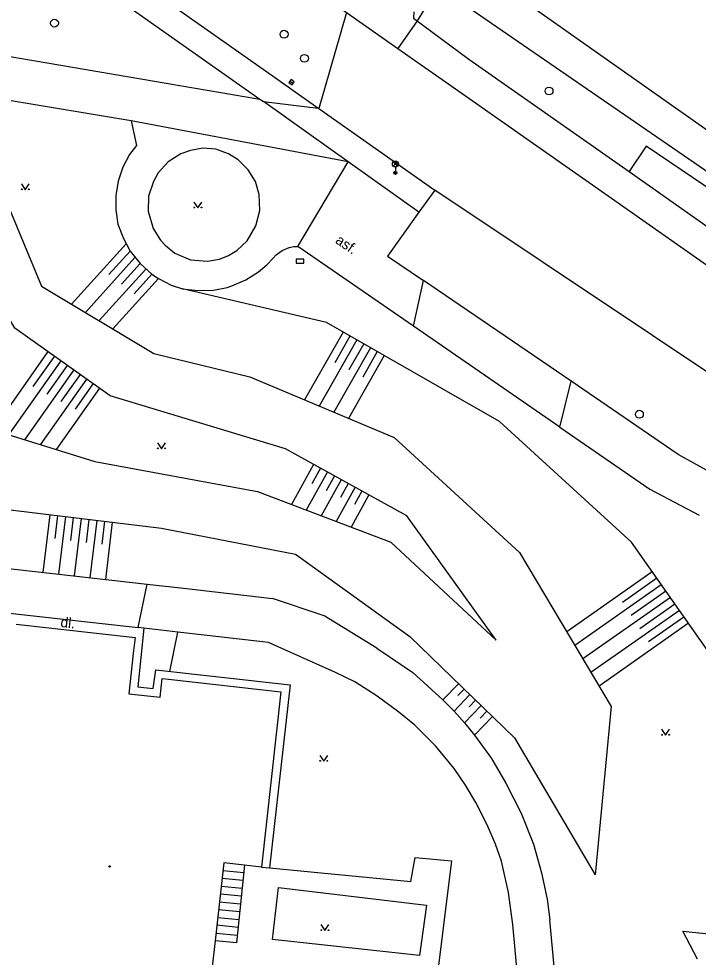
# Model space of a CAD drawing. Extents: x -602419 to -601554, y -1162937 to -1162362.
# Drawn here: x -602003.4 to -601960.3, y -1162582 to -1162522.5 of the extents above; entities that cross this region are included whole.
import ezdxf

# ---------------------------------------------------------------- set-up
doc = ezdxf.new("R2010")
doc.units = 0
doc.layers.add('Podklad', color=7, linetype='Continuous')

msp = doc.modelspace()

# ---------------------------------------------------------------- linework, layer by layer
at = {"layer": 'Podklad'}
for p, q in [((-602001.1665, -1162516.3917), (-601988.13, -1162525.56)), ((-601998.3077, -1162520.4323), (-601988.11, -1162527.62)), ((-601986.2125, -1162526.4685), (-601986.0075, -1162526.6115)), ((-601979.6525, -1162531.86), (-601979.3875, -1162531.595)), ((-601979.6525, -1162531.595), (-601979.3875, -1162531.86)), ((-601979.52, -1162531.915), (-601979.52, -1162532.29))]:
    msp.add_line(p, q, dxfattribs=at)
for points in [[(-601977.7199, -1162516.9), (-601956.9099, -1162531.58), (-601954.44, -1162533.26), (-601952.87, -1162534.1599)], [(-601984.54, -1162520.75), (-601979.57, -1162524.25), (-601975.29, -1162527.25)], [(-601934.5953, -1162546.3375), (-601934.4053, -1162544.2963), (-601934.395, -1162544.1839), (-601934.035, -1162541.6329), (-601941.491, -1162540.521), (-601946.887, -1162539.0499), (-601952.218, -1162537.284), (-601953.5449, -1162536.4029), (-601953.8289, -1162536.2141), (-601956.502, -1162534.4389), (-601976.81, -1162520.475), (-601978.14, -1162522.6591), (-601979.356, -1162524.4)], [(-601987.89, -1162527.76), (-601984.4098, -1162528.1838), (-601984.36, -1162528.1899), (-601982.6096, -1162522.1094)], [(-601978.35, -1162522.08), (-601978.37, -1162522.49), (-601974.85, -1162525.08)], [(-602011.79, -1162523.58), (-601988.11, -1162527.62)], [(-601974.85, -1162525.08), (-601964.68, -1162532.21)], [(-601988.13, -1162525.56), (-601986.98, -1162526.37)], [(-601986.98, -1162526.37), (-601985.88, -1162527.15)], [(-601996.29, -1162529), (-602007.08, -1162527.2)], [(-602007.08, -1162527.2), (-602001.98, -1162539.48), (-601994.84, -1162543.74), (-601988.75, -1162545.23), (-601979.6, -1162549.08), (-601971.65, -1162556.37), (-601965.83, -1162566.14), (-601966.84, -1162576.81)], [(-601985.88, -1162527.15), (-601977.02, -1162533.38), (-601978.04, -1162534.79)], [(-601975.29, -1162527.25), (-601965.81, -1162533.9)], [(-601988.11, -1162527.62), (-601987.89, -1162527.76)], [(-601985.71, -1162536.9699), (-601982.51, -1162531.59), (-601986.26, -1162528.9299), (-601986.49, -1162528.7699), (-601987.89, -1162527.76)], [(-601996.29, -1162529), (-601995.95, -1162530.55)], [(-601978.04, -1162534.79), (-601982.51, -1162531.59), (-601996.29, -1162529)], [(-601995.95, -1162530.55), (-601996.38, -1162531.13), (-601996.82, -1162531.94), (-601997.11, -1162532.81), (-601997.25, -1162533.7199), (-601997.26, -1162534.64), (-601997.13, -1162535.55), (-601996.78, -1162536.46), (-601996.35, -1162537.26), (-601995.7199, -1162538.05), (-601994.9699, -1162538.7199), (-601994.55, -1162539), (-601993.75, -1162539.4099), (-601993.03, -1162539.64)], [(-601992.51, -1162530.87), (-601993.13, -1162531.09)], [(-601991.73, -1162530.7199), (-601992.51, -1162530.87)], [(-601990.9099, -1162530.8), (-601991.73, -1162530.7199)], [(-601990.1, -1162531.08), (-601990.9099, -1162530.8)], [(-601963.6, -1162530.6), (-601964.68, -1162532.21)], [(-601963.6, -1162530.6), (-601964.68, -1162532.21)], [(-601957.74, -1162534.57), (-601963.6, -1162530.6)], [(-601993.13, -1162531.09), (-601993.93, -1162531.6)], [(-601989.5, -1162531.4699), (-601990.1, -1162531.08)], [(-601988.87, -1162532.1), (-601989.5, -1162531.4699)], [(-601993.93, -1162531.6), (-601994.58, -1162532.3)], [(-601994.58, -1162532.3), (-601994.86, -1162532.85)], [(-601988.4, -1162532.83), (-601988.87, -1162532.1)], [(-601964.68, -1162532.21), (-601958.95, -1162536.24)], [(-602003.25, -1162532.985), (-602003, -1162533.36), (-602002.75, -1162532.985)], [(-601994.86, -1162532.85), (-601995.18, -1162533.76)], [(-601988.1599, -1162533.6599), (-601988.4, -1162532.83)], [(-601995.18, -1162533.76), (-601995.2, -1162534.7199)], [(-601988.13, -1162534.67), (-601988.1599, -1162533.6599)], [(-601956.34, -1162547.2), (-601977.02, -1162533.38)], [(-601992.3, -1162534.145), (-601992.05, -1162534.52), (-601991.8, -1162534.145)], [(-601965.81, -1162533.9), (-601958, -1162539.37), (-601957.2, -1162539.88)], [(-601973.12, -1162561.93), (-601978.8, -1162554.04), (-601986.49, -1162549.8), (-601997.61, -1162546.43), (-602003.6599, -1162542.15), (-602007.98, -1162534.7199)], [(-601995.2, -1162534.7199), (-601994.89, -1162535.83)], [(-601988.37, -1162535.65), (-601988.13, -1162534.67)], [(-601978.04, -1162534.79), (-601980.03, -1162537.57), (-601977.73, -1162539.11)], [(-601988.92, -1162536.61), (-601988.37, -1162535.65)], [(-601994.89, -1162535.83), (-601994.42, -1162536.55)], [(-601996.61, -1162536.8), (-602000.07, -1162540.62)], [(-601994.42, -1162536.55), (-601994.13, -1162536.87)], [(-601989.57, -1162537.21), (-601988.92, -1162536.61)], [(-601996.35, -1162537.26), (-601997.69, -1162538.73)], [(-601994.13, -1162536.87), (-601993.52, -1162537.39)], [(-601993.52, -1162537.39), (-601992.52, -1162537.81)], [(-601993.03, -1162539.64), (-601992.05, -1162539.75), (-601991.05, -1162539.73), (-601990.19, -1162539.56), (-601989.89, -1162539.45), (-601989.01, -1162539.07), (-601988.2, -1162538.56), (-601987.68, -1162538.13), (-601987.27, -1162537.7), (-601987.09, -1162537.49), (-601986.7, -1162537.21), (-601986.26, -1162537.02), (-601985.9699, -1162536.96), (-601985.71, -1162536.9699)], [(-601990.1, -1162537.53), (-601989.57, -1162537.21)], [(-601978.38, -1162542.02), (-601985.71, -1162536.9699)], [(-601996.05, -1162537.67), (-601999.19, -1162541.14)], [(-601992.52, -1162537.81), (-601991.45, -1162537.9)], [(-601991.45, -1162537.9), (-601990.68, -1162537.76)], [(-601990.68, -1162537.76), (-601990.1, -1162537.53)], [(-601995.36, -1162538.4), (-601998.32, -1162541.6599)], [(-601995.7199, -1162538.05), (-601996.89, -1162539.35)], [(-601994.55, -1162539), (-601997.44, -1162542.19)], [(-601994.9699, -1162538.7199), (-601996.1, -1162539.96)], [(-601978.38, -1162542.02), (-601977.73, -1162539.11)], [(-601968.36, -1162545.51), (-601977.73, -1162539.11)], [(-601959.05, -1162563.54), (-601964.54, -1162555.71), (-601972.92, -1162548.05), (-601983.89, -1162541.79), (-601993.03, -1162539.64)], [(-601969.08, -1162548.43), (-601978.38, -1162542.02)], [(-601982.84, -1162542.39), (-601985.29, -1162546.69)], [(-601982.4, -1162542.64), (-601983.37, -1162544.34)], [(-601981.9699, -1162542.89), (-601984.36, -1162547.08)], [(-601981.1, -1162543.38), (-601983.43, -1162547.4699)], [(-601981.53, -1162543.13), (-601982.48, -1162544.79)], [(-602008.99, -1162543.69), (-602004.8, -1162548.68), (-601998.59, -1162550.6), (-601988.27, -1162552.51), (-601979.81, -1162555.7199), (-601973.12, -1162561.93)], [(-602001.56, -1162543.63), (-602004.98, -1162548.4699)], [(-602001.15, -1162543.92), (-602002.52, -1162545.85)], [(-601980.23, -1162543.88), (-601982.5, -1162547.86)], [(-601980.67, -1162543.63), (-601981.59, -1162545.24)], [(-602000.74, -1162544.21), (-602004.07, -1162548.9099)], [(-602000.34, -1162544.5), (-602001.63, -1162546.33)], [(-601999.93, -1162544.79), (-602003.06, -1162549.2199)], [(-601999.52, -1162545.08), (-602000.74, -1162546.8)], [(-601999.11, -1162545.37), (-602002.06, -1162549.53)], [(-601998.7, -1162545.6599), (-601999.84, -1162547.27)], [(-601969.08, -1162548.43), (-601968.36, -1162545.51)], [(-601959.59, -1162551.26), (-601961.57, -1162550.15), (-601968.36, -1162545.51)], [(-601998.3, -1162545.94), (-602001.05, -1162549.84)], [(-601969.08, -1162548.43), (-601963.38, -1162552.36), (-601960.25, -1162553.99)], [(-601994.61, -1162549.415), (-601994.36, -1162549.79), (-601994.11, -1162549.415)], [(-601984.71, -1162550.78), (-601986.11, -1162553.33)], [(-601984.27, -1162551.02), (-601984.82, -1162552.02)], [(-601983.83, -1162551.26), (-601985.17, -1162553.69)], [(-601983.39, -1162551.51), (-601983.9099, -1162552.45)], [(-601982.96, -1162551.75), (-601984.2199, -1162554.04)], [(-601982.08, -1162552.23), (-601983.28, -1162554.4)], [(-601982.52, -1162551.99), (-601983.01, -1162552.88)], [(-601981.21, -1162552.71), (-601982.33, -1162554.76)], [(-601981.64, -1162552.4699), (-601982.11, -1162553.32)], [(-602010.34, -1162555.63), (-602007.11, -1162553.29), (-601994.36, -1162554.83), (-601985.86, -1162556.4699), (-601978.6, -1162561.69), (-601971.9699, -1162568.12), (-601966.84, -1162576.81)], [(-602001.45, -1162553.9699), (-602001.89, -1162557.63)], [(-602000.95, -1162554.03), (-602001.13, -1162555.49)], [(-602000.46, -1162554.09), (-602000.9, -1162557.74)], [(-601999.96, -1162554.15), (-602000.14, -1162555.61)], [(-601999.46, -1162554.21), (-601999.9, -1162557.85)], [(-601998.9699, -1162554.27), (-601999.14, -1162555.73)], [(-601998.4699, -1162554.33), (-601998.9099, -1162557.9699)], [(-601997.9699, -1162554.39), (-601998.15, -1162555.85)], [(-601997.48, -1162554.45), (-601997.92, -1162558.08)], [(-602008.37, -1162556.9), (-601995.27, -1162558.38)], [(-601963.2199, -1162557.59), (-601968.65, -1162561.4)], [(-601962.93, -1162558), (-601965.12, -1162559.53)], [(-601995.83, -1162561.13), (-601995.27, -1162558.38)], [(-601995.27, -1162558.38), (-601992.78, -1162558.6599)], [(-601992.78, -1162558.6599), (-601987.31, -1162559.28)], [(-601962.65, -1162558.4099), (-601968.14, -1162562.26)], [(-601962.36, -1162558.82), (-601964.57, -1162560.37)], [(-601980.7, -1162562.43), (-601984.04, -1162560.39), (-601987.31, -1162559.28)], [(-601962.07, -1162559.23), (-601967.63, -1162563.12)], [(-601961.5, -1162560.05), (-601967.11, -1162563.98)], [(-601961.79, -1162559.64), (-601964.02, -1162561.2)], [(-602004.01, -1162560.21), (-601995.83, -1162561.13)], [(-601961.21, -1162560.46), (-601963.4699, -1162562.04)], [(-602003.58, -1162560.9099), (-601996.04, -1162561.75)], [(-601995.48, -1162561.17), (-601995.87, -1162564.88), (-601994.88, -1162565), (-601994.71, -1162563.81), (-601986.2, -1162564.76), (-601987.51, -1162576.37)], [(-601995.48, -1162561.17), (-601995.83, -1162561.13)], [(-601993.33, -1162561.42), (-601995.48, -1162561.17)], [(-601960.93, -1162560.86), (-601966.6, -1162564.84)], [(-601996.04, -1162561.75), (-601996.15, -1162562.77)], [(-601993.8199, -1162563.9094), (-601993.33, -1162561.42)], [(-601987.57, -1162562.07), (-601993.33, -1162561.42)], [(-601983.32, -1162563.9699), (-601987.57, -1162562.07)], [(-601980.7, -1162562.43), (-601978.4099, -1162563.9699), (-601976.5, -1162565.71), (-601975.8, -1162566.42), (-601975.13, -1162567.17), (-601974.49, -1162567.95), (-601973.43, -1162569.43), (-601972.51, -1162571), (-601971.54, -1162572.89), (-601970.76, -1162574.87), (-601970.26, -1162576.69), (-601969.9, -1162578.36), (-601969.7199, -1162579.67)], [(-601996.15, -1162562.77), (-601996.44, -1162565.33)], [(-601971.92, -1162581.56), (-601972.07, -1162579.95), (-601972.35, -1162577.94), (-601972.79, -1162575.95), (-601973.1599, -1162574.86), (-601973.69, -1162573.64), (-601974.42, -1162572.2199), (-601975.07, -1162571.12), (-601975.8, -1162570.07), (-601976.9699, -1162568.63), (-601978.29, -1162567.31), (-601979.3, -1162566.49), (-601980.67, -1162565.48), (-601982.1, -1162564.58), (-601983.32, -1162563.9699)], [(-601994.45, -1162565.55), (-601994.31, -1162564.36)], [(-601994.31, -1162564.36), (-601993.92, -1162564.4)], [(-601993.92, -1162564.4), (-601986.78, -1162565.2)], [(-601975.51, -1162564.69), (-601976.5, -1162565.71)], [(-601996.44, -1162565.33), (-601994.45, -1162565.55)], [(-601986.78, -1162565.2), (-601988.02, -1162576.32)], [(-601974.79, -1162565.38), (-601975.8, -1162566.42)], [(-601975.15, -1162565.03), (-601975.55, -1162565.44)], [(-601974.43, -1162565.73), (-601974.84, -1162566.1599)], [(-601974.07, -1162566.08), (-601975.13, -1162567.17)], [(-601973.71, -1162566.43), (-601974.15, -1162566.88)], [(-601973.35, -1162566.77), (-601974.49, -1162567.95)], [(-601962.63, -1162567.575), (-601962.38, -1162567.95), (-601962.13, -1162567.575)], [(-601984.3109, -1162569.2353), (-601984.0609, -1162569.6103), (-601983.8109, -1162569.2353)], [(-601961.29, -1162580.38), (-601936.76, -1162582.92), (-601934.34, -1162572.48), (-601913.36, -1162573.8), (-601913.26, -1162588.85)], [(-601990.4, -1162576.05), (-601990.96, -1162580.99)], [(-601989.09, -1162576.2), (-601990.4, -1162576.05)], [(-601978.53, -1162577.23), (-601978.27, -1162575.7199)], [(-601978.27, -1162575.7199), (-601975.96, -1162575.93)], [(-601975.96, -1162575.93), (-601977, -1162584.26)], [(-601990.46, -1162576.54), (-601989.14, -1162576.67)], [(-601989.09, -1162576.2), (-601989.6, -1162581.13)], [(-601988.02, -1162576.32), (-601989.09, -1162576.2)], [(-601988.02, -1162576.32), (-601987.51, -1162576.37)], [(-601987.51, -1162576.37), (-601978.53, -1162577.23)], [(-601989.19, -1162577.17), (-601990.51, -1162577.04)], [(-601990.57, -1162577.53), (-601989.24, -1162577.6599)], [(-601987.31, -1162580.9099), (-601986.94, -1162577.61), (-601977.54, -1162578.73), (-601977.98, -1162581.92), (-601987.31, -1162580.9099)], [(-601989.3, -1162578.1599), (-601990.62, -1162578.03)], [(-601989.4, -1162579.15), (-601990.73, -1162579.02)], [(-601990.68, -1162578.52), (-601989.35, -1162578.65)], [(-601990.79, -1162579.51), (-601989.45, -1162579.65)], [(-601971.36, -1162587.62), (-601969.02, -1162587.19), (-601969.7199, -1162579.67)], [(-601989.5, -1162580.14), (-601990.84, -1162580)], [(-601984.24, -1162579.965), (-601983.99, -1162580.34), (-601983.74, -1162579.965)], [(-601990.9, -1162580.5), (-601989.55, -1162580.64)], [(-601960.36, -1162582.15), (-601961.29, -1162580.38)], [(-601990.96, -1162580.99), (-601991.1599, -1162582.81)], [(-601989.6, -1162581.13), (-601990.96, -1162580.99)], [(-601971.36, -1162587.62), (-601971.92, -1162581.56)]]:
    msp.add_lwpolyline(points, dxfattribs=at)
for points in [[(-601986.284, -1162526.571), (-601986.079, -1162526.714), (-601985.936, -1162526.509), (-601986.141, -1162526.366)], [(-601985.82, -1162538.025), (-601985.32, -1162538.025), (-601985.32, -1162537.775), (-601985.82, -1162537.775)]]:
    msp.add_lwpolyline(points, close=True, dxfattribs=at)
for centre, radius in [((-602001.15, -1162522.8), 0.25), ((-601986.58, -1162523.5), 0.25), ((-601985.29, -1162525.03), 0.25), ((-601969.77, -1162527.1), 0.25), ((-601979.52, -1162531.7275), 0.1875), ((-601979.52, -1162532.29), 0.1), ((-601979.52, -1162532.29), 0.0723), ((-601979.52, -1162532.29), 0.0438), ((-602003.2251, -1162533.3349), 0.025), ((-602002.7754, -1162533.3349), 0.025), ((-601992.2751, -1162534.4949), 0.025), ((-601991.8254, -1162534.4949), 0.025), ((-601964.04, -1162547.6), 0.25), ((-601994.5851, -1162549.7649), 0.025), ((-601994.1354, -1162549.7649), 0.025), ((-601962.6051, -1162567.9249), 0.025), ((-601962.1554, -1162567.9249), 0.025), ((-601984.286, -1162569.5852), 0.025), ((-601983.8363, -1162569.5852), 0.025), ((-601997.65, -1162576.28), 0.045), ((-601997.65, -1162576.28), 0.0199), ((-601984.2151, -1162580.3149), 0.025), ((-601983.7654, -1162580.3149), 0.025)]:
    msp.add_circle(centre, radius, dxfattribs=at)

# ---------------------------------------------------------------- texts
for s, rotation, p in [('asf.', 325.72, (-601983.3793, -1162536.7049)), ('dl.', 353.64, (-602000.79, -1162561.09))]:
    msp.add_text(s, height=0.65, rotation=rotation, dxfattribs=at).set_placement(p)

doc.saveas('drawing.dxf')
